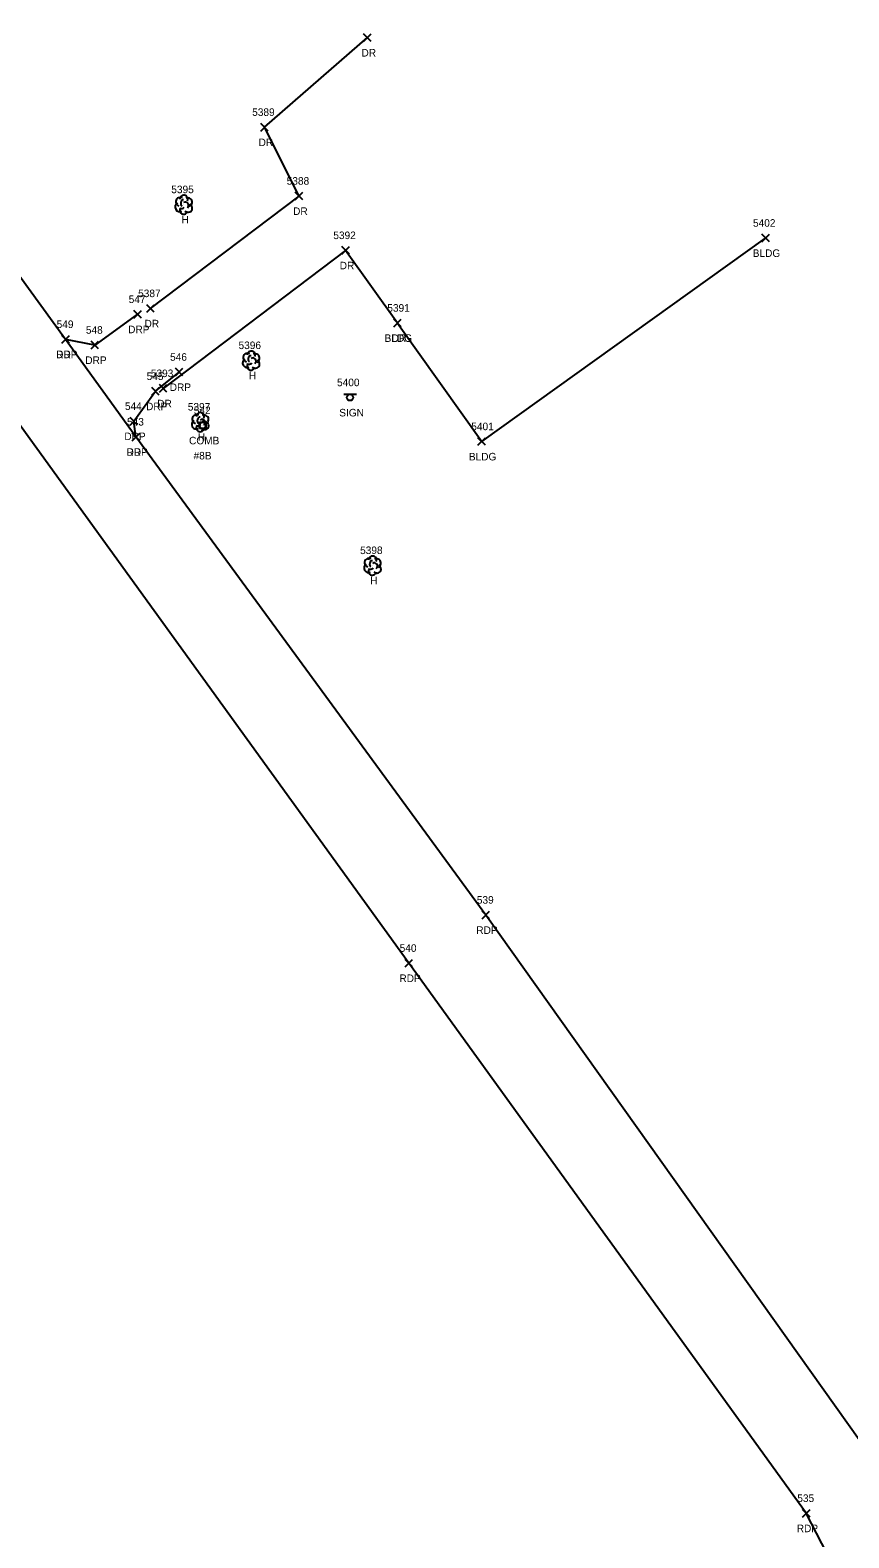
# Model space of a CAD drawing. Extents: x 1481523 to 1489083, y 884156 to 893756.
# Drawn here: x 1487409.3 to 1487626, y 886406.2 to 886805.3 of the extents above; entities that cross this region are included whole.
import ezdxf

# ---------------------------------------------------------------- set-up
doc = ezdxf.new("R2010")
doc.units = 0
for name, color, linetype in [('L_A', 7, 'Continuous'), ('L_I', 7, 'Continuous'), ('L_TIC', 7, 'Continuous'), ('LBC', 7, 'Continuous'), ('LTD', 7, 'Continuous'), ('P_A', 7, 'Continuous'), ('P_I', 7, 'Continuous'), ('P_TIC', 7, 'Continuous'), ('PET', 7, 'Continuous'), ('R_A', 7, 'Continuous'), ('R_I', 7, 'Continuous'), ('R_TIC', 7, 'Continuous'), ('RDP', 7, 'Continuous'), ('S_A', 7, 'Continuous'), ('S_I', 7, 'Continuous'), ('SSGN', 7, 'Continuous'), ('U_A', 7, 'Continuous'), ('U_C', 7, 'Continuous'), ('U_I', 7, 'Continuous'), ('UP', 7, 'Continuous')]:
    doc.layers.add(name, color=color, linetype=linetype)

msp = doc.modelspace()

# ---------------------------------------------------------------- linework, layer by layer
at = {"layer": 'L_TIC'}
for points in [[(1487602.96, 886749.3), (1487604.96, 886751.3)], [(1487604.96, 886749.3), (1487602.96, 886751.3)], [(1487505.51, 886726.81), (1487507.51, 886728.81)], [(1487507.51, 886726.81), (1487505.51, 886728.81)], [(1487527.82, 886695.43), (1487529.82, 886697.43)], [(1487529.82, 886695.43), (1487527.82, 886697.43)]]:
    msp.add_lwpolyline(points, dxfattribs=at)
at = {"layer": 'LBC'}
msp.add_lwpolyline([(1487506.51, 886727.81), (1487528.82, 886696.43), (1487603.96, 886750.3)], dxfattribs=at)
at = {"layer": 'LTD'}
for p, q in [((1487449.9, 886759.18), (1487449.9, 886759.18)), ((1487449.9, 886759.18), (1487449.9, 886759.18)), ((1487467.75, 886717.91), (1487467.75, 886717.91)), ((1487467.75, 886717.91), (1487467.75, 886717.91)), ((1487454.27, 886701.63), (1487454.27, 886701.63)), ((1487454.27, 886701.63), (1487454.27, 886701.63)), ((1487499.88, 886663.64), (1487499.88, 886663.64)), ((1487499.88, 886663.64), (1487499.88, 886663.64))]:
    msp.add_line(p, q, dxfattribs=at)
for centre in [(1487449.95, 886760.61), (1487467.8, 886719.34), (1487454.32, 886703.06), (1487499.93, 886665.07)]:
    msp.add_arc(centre, 1.05, 335.5272, 180.9563, dxfattribs=at)
for centre, major_axis, ratio, start_param, end_param in [((1487449.11, 886759.85), (1.21, -0.51), 0.895232, 1.570796, 4.712389), ((1487449.69, 886759.64), (-0.208, -0.792), 0.645439, 3.141593, 6.283185), ((1487450.4, 886759.01), (-0.5, 0.667), 0.989748, 3.141593, 6.283185), ((1487450.94, 886759.76), (-1.14, -0.48), 0.949671, 1.570796, 4.712389), ((1487448.82, 886758.47), (0.58, -1.04), 0.959034, 3.141593, 6.283185), ((1487449.9, 886757.68), (0.26, 1.06), 0.942809, 1.570796, 4.712389), ((1487449.44, 886758.43), (-0.625, -0.083), 0.423636, 0, 3.141593), ((1487450.9, 886758.35), (-1.09, 0.79), 0.841452, 1.570796, 4.712389), ((1487466.96, 886718.58), (1.21, -0.51), 0.895232, 1.570796, 4.712389), ((1487468.79, 886718.49), (-1.14, -0.48), 0.949671, 1.570796, 4.712389), ((1487466.67, 886717.2), (0.58, -1.04), 0.959034, 3.141593, 6.283185), ((1487467.75, 886716.41), (0.26, 1.06), 0.942809, 1.570796, 4.712389), ((1487467.29, 886717.16), (-0.625, -0.083), 0.423636, 0, 3.141593), ((1487467.54, 886718.37), (-0.208, -0.792), 0.645439, 3.141593, 6.283185), ((1487468.25, 886717.74), (-0.5, 0.667), 0.989748, 3.141593, 6.283185), ((1487468.75, 886717.08), (-1.09, 0.79), 0.841452, 1.570796, 4.712389), ((1487453.48, 886702.3), (1.21, -0.51), 0.895232, 1.570796, 4.712389), ((1487453.19, 886700.92), (0.58, -1.04), 0.959034, 3.141593, 6.283185), ((1487454.27, 886700.13), (0.26, 1.06), 0.942809, 1.570796, 4.712389), ((1487453.81, 886700.88), (-0.625, -0.083), 0.423636, 0, 3.141593), ((1487454.06, 886702.09), (-0.208, -0.792), 0.645439, 3.141593, 6.283185), ((1487454.77, 886701.46), (-0.5, 0.667), 0.989748, 3.141593, 6.283185), ((1487455.27, 886700.8), (-1.09, 0.79), 0.841452, 1.570796, 4.712389), ((1487455.31, 886702.21), (-1.14, -0.48), 0.949671, 1.570796, 4.712389), ((1487498.8, 886662.93), (0.58, -1.04), 0.959034, 3.141593, 6.283185), ((1487499.09, 886664.31), (1.21, -0.51), 0.895232, 1.570796, 4.712389), ((1487499.67, 886664.1), (-0.208, -0.792), 0.645439, 3.141593, 6.283185), ((1487500.38, 886663.47), (-0.5, 0.667), 0.989748, 3.141593, 6.283185), ((1487500.92, 886664.22), (-1.14, -0.48), 0.949671, 1.570796, 4.712389), ((1487499.88, 886662.14), (0.26, 1.06), 0.942809, 1.570796, 4.712389), ((1487499.42, 886662.89), (-0.625, -0.083), 0.423636, 0, 3.141593), ((1487500.88, 886662.81), (-1.09, 0.79), 0.841452, 1.570796, 4.712389)]:
    msp.add_ellipse(centre, major_axis=major_axis, ratio=ratio, start_param=start_param, end_param=end_param, dxfattribs=at)
at = {"layer": 'P_TIC'}
for points in [[(1487417.66, 886722.49), (1487419.66, 886724.49)], [(1487419.66, 886722.49), (1487417.66, 886724.49)], [(1487436.28, 886696.66), (1487438.28, 886698.66)], [(1487438.28, 886696.66), (1487436.28, 886698.66)], [(1487528.89, 886570.08), (1487530.89, 886572.08)], [(1487530.89, 886570.08), (1487528.89, 886572.08)], [(1487508.53, 886557.33), (1487510.53, 886559.33)], [(1487510.53, 886557.33), (1487508.53, 886559.33)], [(1487613.71, 886411.68), (1487615.71, 886413.68)], [(1487615.71, 886411.68), (1487613.71, 886413.68)]]:
    msp.add_lwpolyline(points, dxfattribs=at)
at = {"layer": 'PET'}
for points in [[(1487623.03, 886396.68), (1487614.71, 886412.68), (1487509.53, 886558.33), (1487399.2, 886710.79), (1487304.98, 886841.59), (1487249.25, 886918.99), (1487138.6, 887072.86), (1487086.89, 887144.79), (1486969.76, 887307.16), (1486903.3, 887400.42), (1486868.78, 887451.35), (1486836.4, 887503.18), (1486808.87, 887552.94), (1486786.32, 887598.75), (1486760.43, 887659.94), (1486738.28, 887720.05), (1486718.2, 887787.22), (1486705.95, 887838.78), (1486696.04, 887887.03), (1486682.75, 887959.61), (1486658.25, 888100.78)], [(1488003.32, 886636.97), (1487852.05, 886528.58), (1487797.99, 886489.79), (1487684.52, 886408.29), (1487667.06, 886408.07), (1487641.38, 886417.92), (1487632.47, 886426.93), (1487529.89, 886571.08), (1487437.28, 886697.66), (1487418.66, 886723.49), (1487368.4, 886792.53), (1487324.38, 886853.98), (1487266.69, 886933.92), (1487190.62, 887040.47), (1487157.21, 887086.8), (1487121.09, 887136.63)]]:
    msp.add_lwpolyline(points, dxfattribs=at)
at = {"layer": 'R_TIC'}
for points in [[(1487497.55, 886802.36), (1487499.55, 886804.36)], [(1487499.55, 886802.36), (1487497.55, 886804.36)], [(1487470.32, 886778.64), (1487472.32, 886780.64)], [(1487472.32, 886778.64), (1487470.32, 886780.64)], [(1487479.45, 886760.43), (1487481.45, 886762.43)], [(1487481.45, 886760.43), (1487479.45, 886762.43)], [(1487491.79, 886746.03), (1487493.79, 886748.03)], [(1487493.79, 886746.03), (1487491.79, 886748.03)], [(1487440.12, 886730.66), (1487442.12, 886732.66)], [(1487442.12, 886730.66), (1487440.12, 886732.66)], [(1487436.72, 886729.11), (1487438.72, 886731.11)], [(1487438.72, 886729.11), (1487436.72, 886731.11)], [(1487505.51, 886726.81), (1487507.51, 886728.81)], [(1487507.51, 886726.81), (1487505.51, 886728.81)], [(1487417.66, 886722.49), (1487419.66, 886724.49)], [(1487419.66, 886722.49), (1487417.66, 886724.49)], [(1487425.4, 886720.97), (1487427.4, 886722.97)], [(1487427.4, 886720.97), (1487425.4, 886722.97)], [(1487447.73, 886713.82), (1487449.73, 886715.82)], [(1487449.73, 886713.82), (1487447.73, 886715.82)], [(1487441.47, 886708.73), (1487443.47, 886710.73)], [(1487443.47, 886708.73), (1487441.47, 886710.73)], [(1487443.49, 886709.49), (1487445.49, 886711.49)], [(1487445.49, 886709.49), (1487443.49, 886711.49)], [(1487435.72, 886700.8), (1487437.72, 886702.8)], [(1487437.72, 886700.8), (1487435.72, 886702.8)], [(1487436.28, 886696.66), (1487438.28, 886698.66)], [(1487438.28, 886696.66), (1487436.28, 886698.66)]]:
    msp.add_lwpolyline(points, dxfattribs=at)
at = {"layer": 'RDP'}
for points in [[(1487441.12, 886731.66), (1487480.45, 886761.43), (1487471.32, 886779.64), (1487498.55, 886803.36)], [(1487506.51, 886727.81), (1487492.79, 886747.03), (1487444.49, 886710.49)], [(1487437.72, 886730.11), (1487426.4, 886721.97), (1487418.66, 886723.49)], [(1487437.28, 886697.66), (1487436.72, 886701.8), (1487442.47, 886709.73), (1487448.73, 886714.82)]]:
    msp.add_lwpolyline(points, dxfattribs=at)
at = {"layer": 'SSGN'}
for p, q in [((1487492.31, 886708.93), (1487495.65, 886708.93)), ((1487493.96, 886708.1), (1487493.96, 886708.1))]:
    msp.add_line(p, q, dxfattribs=at)
msp.add_circle((1487493.96, 886708.1), 0.833, dxfattribs=at)
at = {"layer": 'UP'}
for p, q in [((1487454.12, 886699.85), (1487454.12, 886701.52)), ((1487454.12, 886701.52), (1487455.78, 886701.52)), ((1487455.78, 886699.85), (1487454.12, 886699.85)), ((1487454.7, 886699.02), (1487454.95, 886699.85)), ((1487455.2, 886702.35), (1487454.95, 886701.52)), ((1487454.95, 886700.69), (1487454.95, 886700.69)), ((1487455.78, 886701.52), (1487455.78, 886699.85))]:
    msp.add_line(p, q, dxfattribs=at)
msp.add_circle((1487454.95, 886700.69), 0.833, dxfattribs=at)

# ---------------------------------------------------------------- texts
at = {"layer": 'L_A'}
for s, p in [('H', (1487449.33, 886754.18)), ('BLDG', (1487600.55, 886745.3)), ('BLDG', (1487503.1, 886722.81)), ('H', (1487467.18, 886712.91)), ('H', (1487453.7, 886696.63)), ('BLDG', (1487525.41, 886691.43)), ('H', (1487499.31, 886658.64))]:
    msp.add_text(s, height=2, dxfattribs=at).set_placement(p)
at = {"layer": 'L_I'}
for s, p in [('5395', (1487446.64, 886762.18)), ('5402', (1487600.62, 886753.3)), ('5391', (1487503.82, 886730.81)), ('5396', (1487464.44, 886720.91)), ('5397', (1487451.01, 886704.63)), ('5401', (1487526.05, 886699.43)), ('5398', (1487496.62, 886666.64))]:
    msp.add_text(s, height=2, dxfattribs=at).set_placement(p)
at = {"layer": 'P_A'}
for p in [(1487416.15, 886718.49), (1487434.77, 886692.66), (1487527.38, 886566.08), (1487507.02, 886553.33), (1487612.2, 886407.68)]:
    msp.add_text('RDP', height=2, dxfattribs=at).set_placement(p)
at = {"layer": 'P_I'}
for s, p in [('549', (1487416.29, 886726.49)), ('543', (1487434.92, 886700.66)), ('539', (1487527.52, 886574.08)), ('540', (1487507.09, 886561.33)), ('535', (1487612.35, 886415.68))]:
    msp.add_text(s, height=2, dxfattribs=at).set_placement(p)
at = {"layer": 'R_A'}
for s, p in [('DR', (1487496.98, 886798.36)), ('DR', (1487469.75, 886774.64)), ('DR', (1487478.88, 886756.43)), ('DR', (1487491.22, 886742.03)), ('DR', (1487439.55, 886726.66)), ('DRP', (1487435.21, 886725.11)), ('DR', (1487504.94, 886722.81)), ('DRP', (1487416.15, 886718.49)), ('DRP', (1487423.88, 886716.97)), ('DRP', (1487446.22, 886709.82)), ('DRP', (1487439.96, 886704.73)), ('DR', (1487442.92, 886705.49)), ('DRP', (1487434.21, 886696.8)), ('DRP', (1487434.77, 886692.66))]:
    msp.add_text(s, height=2, dxfattribs=at).set_placement(p)
at = {"layer": 'R_I'}
for s, p in [('5389', (1487468.05, 886782.64)), ('5388', (1487477.19, 886764.43)), ('5392', (1487489.53, 886750.03)), ('5387', (1487437.86, 886734.66)), ('547', (1487435.36, 886733.11)), ('5391', (1487503.82, 886730.81)), ('549', (1487416.29, 886726.49)), ('548', (1487424.03, 886724.97)), ('546', (1487446.32, 886717.82)), ('545', (1487440.11, 886712.73)), ('5393', (1487441.23, 886713.49)), ('544', (1487434.36, 886704.8)), ('543', (1487434.92, 886700.66))]:
    msp.add_text(s, height=2, dxfattribs=at).set_placement(p)
at = {"layer": 'S_A'}
msp.add_text('SIGN', height=2, dxfattribs=at).set_placement((1487491.1, 886703.08))
at = {"layer": 'S_I'}
msp.add_text('5400', height=2, dxfattribs=at).set_placement((1487490.51, 886711.08))
at = {"layer": 'U_A'}
msp.add_text('COMB', height=2, dxfattribs=at).set_placement((1487451.34, 886695.69))
at = {"layer": 'U_C'}
msp.add_text('#8B', height=2, dxfattribs=at).set_placement((1487452.53, 886691.69))
at = {"layer": 'U_I'}
msp.add_text('542', height=2, dxfattribs=at).set_placement((1487452.59, 886703.69))

doc.saveas('drawing.dxf')
